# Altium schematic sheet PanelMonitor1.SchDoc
size 431 x 279 mm; Date: Not shown in title block; ApprovedBy: Not shown in title block; CheckedBy: Not shown in title block; Author: Not shown in title block; CompanyName: Not shown in title block; Engineer: Not shown in title block; Organization: Not shown in title block; Address1: Not shown in title block; Address2: Not shown in title block; Address3: Not shown in title block; Address4: Not shown in title block; DocumentNumber: 1; Revision: Use project parameter SCH_Rev; SheetNumber: 2; SheetTotal: 3; PageSetup: Record=PageOptions¦CenterHorizontal=True¦CenterVertical=True¦PrintScale=0.64¦XCorrection=1.00¦YCorrection=1.00¦PrintKind=0¦BorderSize=5000000¦LeftOffset=0¦BottomOffset=0¦Orientation=2¦PaperLength=1000¦PaperWidth=1000¦Scale=100¦PaperSource=15¦PrintQuality=600¦MediaType=1¦DitherType=10¦PrintScaleMode=1¦PaperKind=Letter
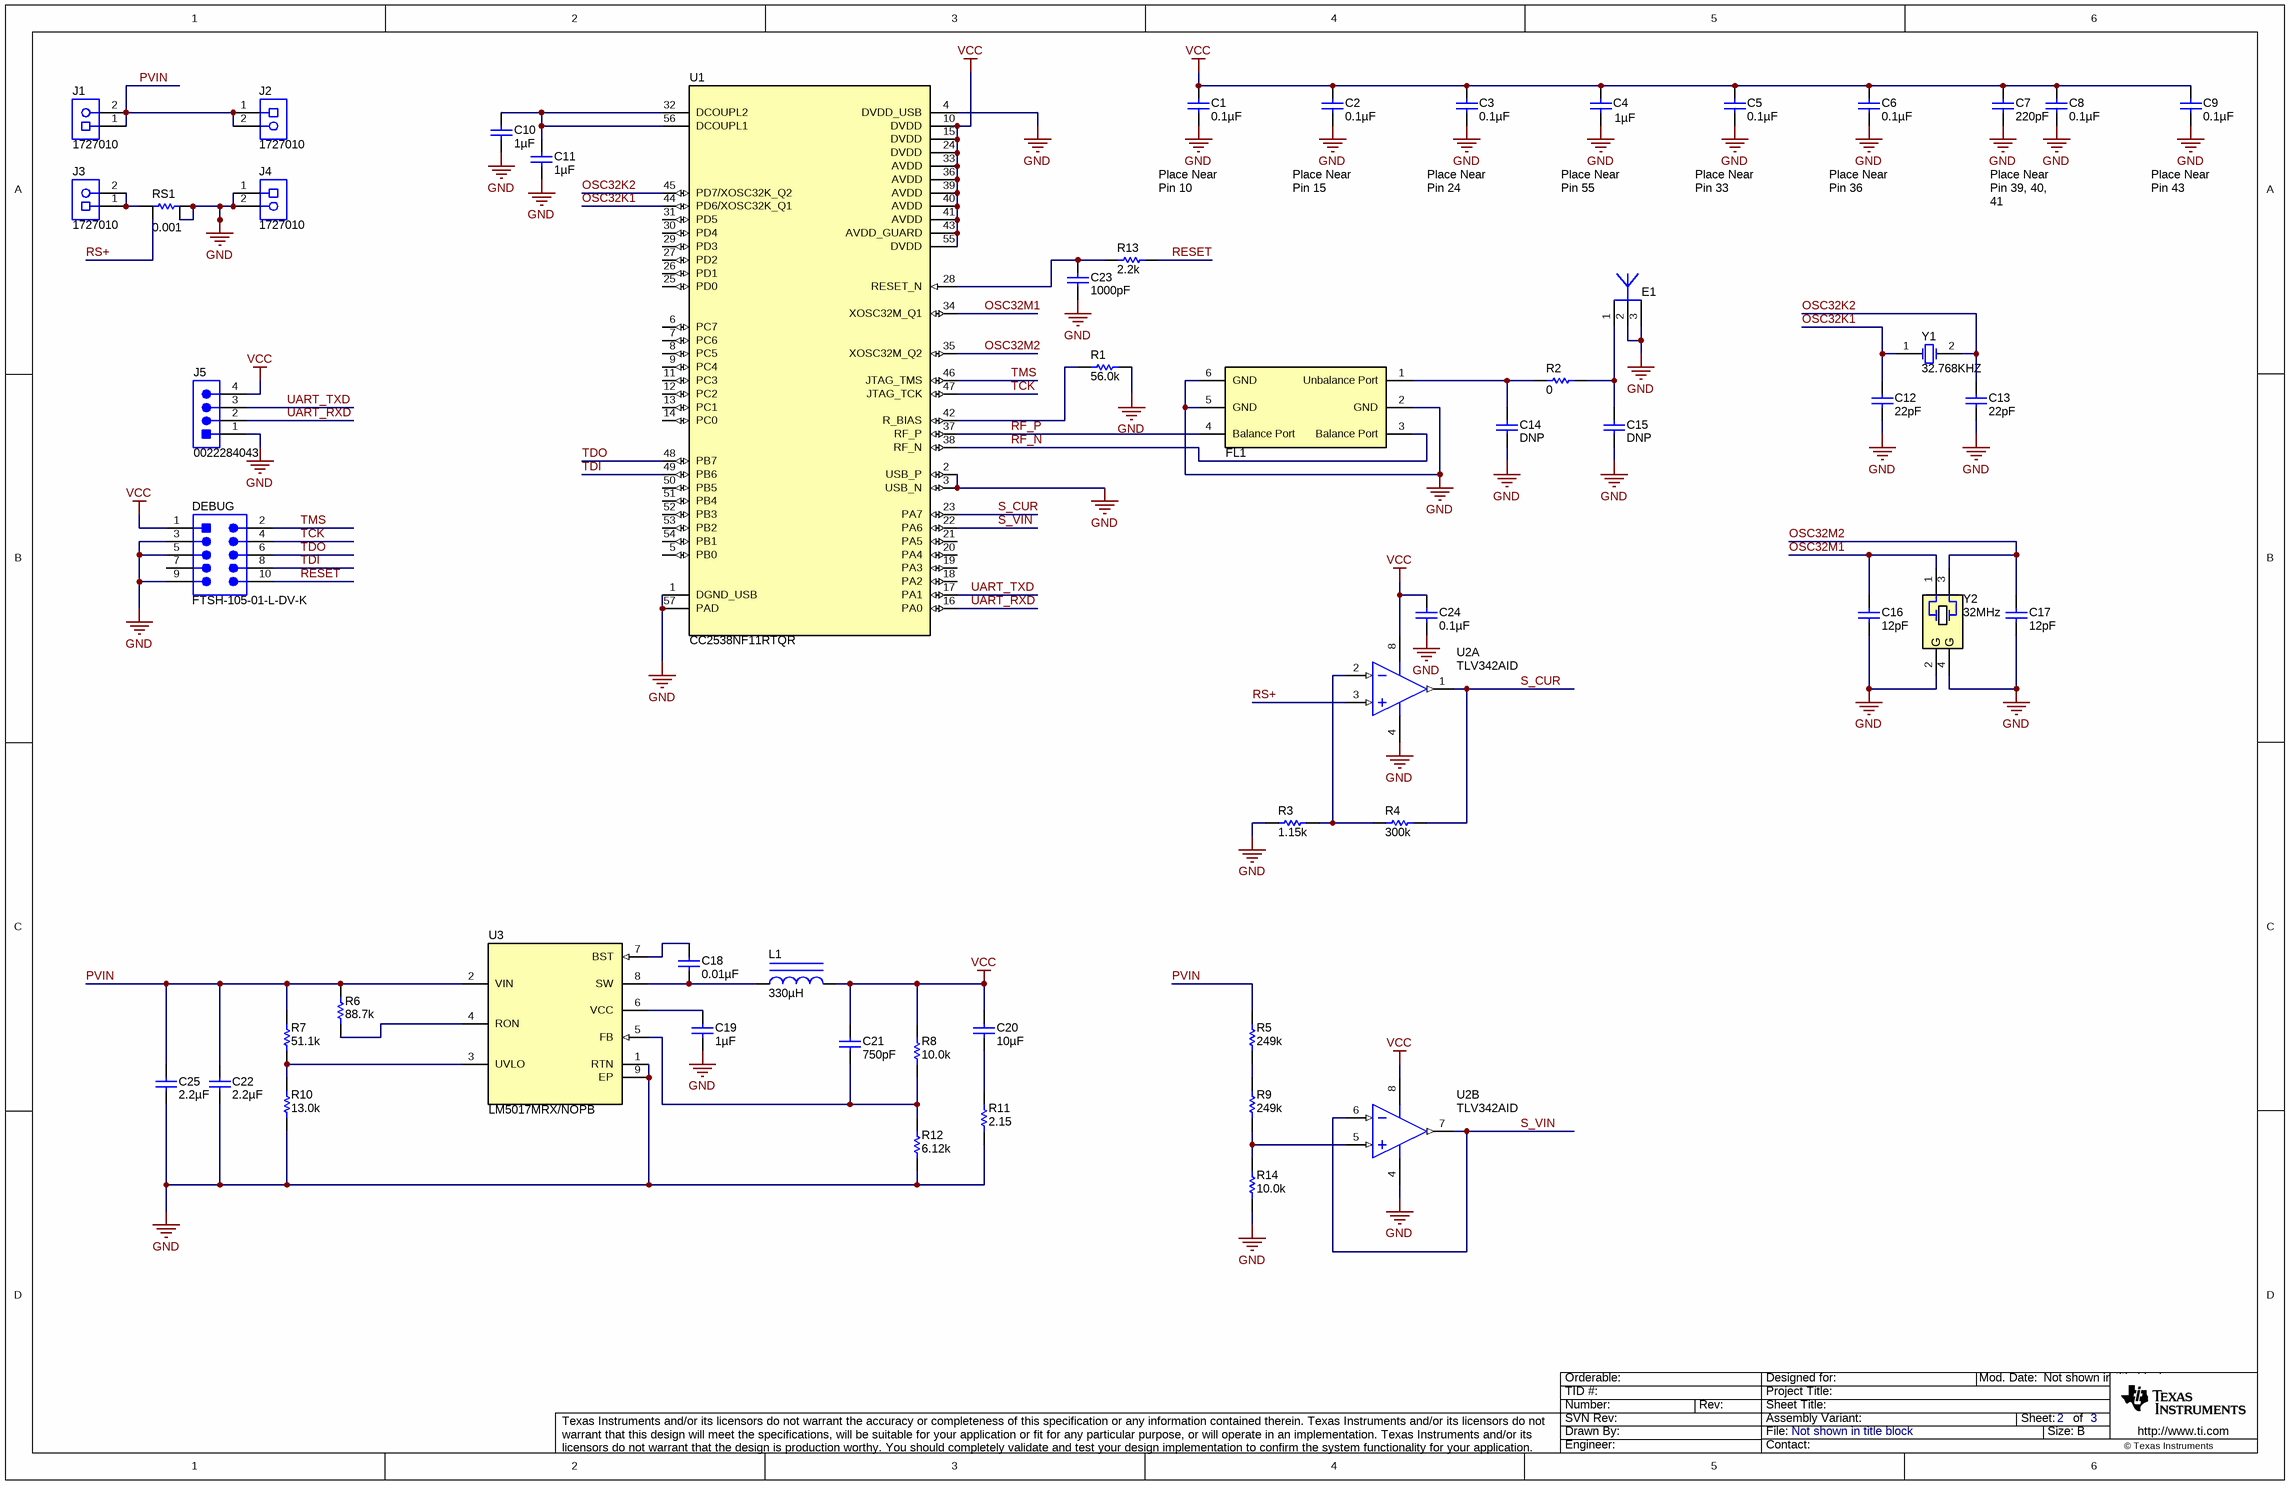
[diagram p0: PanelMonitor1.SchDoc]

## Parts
C1  ValueDisplayed: 0.1µF  [0402]  (hidden comment: GRM155R70J104KA01D)
C2  ValueDisplayed: 0.1µF  [0402]  (hidden comment: GRM155R70J104KA01D)
C3  ValueDisplayed: 0.1µF  [0402]  (hidden comment: GRM155R70J104KA01D)
C4  ValueDisplayed: 1µF  [0402]  (hidden comment: GRM155R61A105KE15D)
C5  ValueDisplayed: 0.1µF  [0402]  (hidden comment: GRM155R70J104KA01D)
C6  ValueDisplayed: 0.1µF  [0402]  (hidden comment: GRM155R70J104KA01D)
C7  ValueDisplayed: 220pF  [0402]  (hidden comment: GRM1555C1H221JA01D)
C8  ValueDisplayed: 0.1µF  [0402]  (hidden comment: GRM155R70J104KA01D)
C9  ValueDisplayed: 0.1µF  [0402]  (hidden comment: GRM155R70J104KA01D)
C10  ValueDisplayed: 1µF  [0402]  (hidden comment: GRM155R61A105KE15D)
C11  ValueDisplayed: 1µF  [0402]  (hidden comment: GRM155R61A105KE15D)
C12  ValueDisplayed: 22pF  [0402]  (hidden comment: GRM1555C1H220JA01D)
C13  ValueDisplayed: 22pF  [0402]  (hidden comment: GRM1555C1H220JA01D)
C14  ValueDisplayed: DNP  [0402]  (hidden comment: 0402YC132KAT2A)
C15  ValueDisplayed: DNP  [0402]  (hidden comment: 0402YC132KAT2A)
C16  ValueDisplayed: 12pF  [0402]  (hidden comment: GRM1555C1H120JA01D)
C17  ValueDisplayed: 12pF  [0402]  (hidden comment: GRM1555C1H120JA01D)
C18  ValueDisplayed: 0.01µF  [0402]  (hidden comment: GRM155R61C103KA01D)
C19  ValueDisplayed: 1µF  [0603]  (hidden comment: GRM188R61C105KA93D)
C20  ValueDisplayed: 10µF  [0603]  (hidden comment: GRM188R60J106ME47D)
C21  ValueDisplayed: 750pF  [0402]  (hidden comment: GRM1555C1H751JA01D)
C22  ValueDisplayed: 2.2µF  [1210_270]  (hidden comment: GRM32ER72A225KA35L)
C23  ValueDisplayed: 1000pF  [0402]  (hidden comment: GRM155R71H102KA01D)
C24  ValueDisplayed: 0.1µF  [0402]  (hidden comment: C0402C104K4RACAUTO)
C25  ValueDisplayed: 2.2µF  [1210_270]  (hidden comment: GRM32ER72A225KA35L)
DEBUG  FTSH-105-01-L-DV-K  [Samtec_FTSH-105-01-x-DV-K]
E1  ANTENNA_DN007A  [ANTENNA_DN007A]  (value not drawn)  (net tie)
FL1  LFB182G45BG5D920  [Murata_LFB182G45BG5D920]  (value not drawn)
J1  1727010  [PhoenixConact_1727010]
J2  1727010  [PhoenixConact_1727010]
J3  1727010  [PhoenixConact_1727010]
J4  1727010  [PhoenixConact_1727010]
J5  0022284043  [Molex_0022284043]
L1  ValueDisplayed: 330µH  [LPS5030]  (hidden comment: LPS5030-334MLB)
R1  ValueDisplayed: 56.0k  [0402]  (hidden comment: RK73H1ETTP5602F)
R2  ValueDisplayed: 0  [0402]  (hidden comment: CRCW04020000Z0ED)
R3  ValueDisplayed: 1.15k  [0402]  (hidden comment: CRCW04021K15FKED)
R4  ValueDisplayed: 300k  [0402]  (hidden comment: CRCW0402300KFKED)
R5  ValueDisplayed: 249k  [1206]  (hidden comment: CRCW1206249KFKEA)
R6  ValueDisplayed: 88.7k  [0402]  (hidden comment: CRCW040288K7FKED)
R7  ValueDisplayed: 51.1k  [0402]  (hidden comment: CRCW040251K1FKED)
R8  ValueDisplayed: 10.0k  [0402]  (hidden comment: CRCW040210K0FKED)
R9  ValueDisplayed: 249k  [1206]  (hidden comment: CRCW1206249KFKEA)
R10  ValueDisplayed: 13.0k  [0402]  (hidden comment: CRCW040213K0FKED)
R11  ValueDisplayed: 2.15  [0402]  (hidden comment: CRCW04022R15FKED)
R12  ValueDisplayed: 6.12k  [0805_HV]  (hidden comment: RT0805BRD076K12L)
R13  ValueDisplayed: 2.2k  [0402]  (hidden comment: CRCW04022K20JNED)
R14  ValueDisplayed: 10.0k  [0805_HV]  (hidden comment: ERJ-6ENF1002V)
RS1  ValueDisplayed: 0.001  [LRMAP3920B-R001FT]  (hidden comment: LRMAP3920B-R001FT)
U1  CC2538NF11RTQR  [RTQ0056C]
U2  TLV342AID  [D0008A_N]  (parts A,B of 2)
U3  LM5017MRX/NOPB  [DDA0008B_N]
Y1  Frequency: 32.768KHZ  [Epson_FC-12M]  (hidden comment: FC-12M 32.7680KA-A3)
Y2  Frequency: 32MHz  [Epson_FA-128]  (hidden comment: FA-128 32.0000MF20X-K3)

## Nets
GND: C1.2 C2.2 C3.2 C4.2 C5.2 C6.2 C7.2 C8.2 C9.2 C10.2 C11.2 C12.2 C13.2 C14.2 C15.2 C16.2 C17.2 C19.2 C22.1 C23.2 C24.2 C25.1 DEBUG.3 DEBUG.5 DEBUG.9 E1.2 E1.3 FL1.2(GND) FL1.5(GND) FL1.6(GND) J4.1 J4.2 J5.1 R1.2 R3.1 R10.1 R11.1 R12.1 R14.1 RS1.1 RS1.3 U1.1(DGND_USB) U1.2(USB_P) U1.3(USB_N) U1.4(DVDD_USB) U1.57(PAD) U2.4(GND) U3.1(RTN) U3.9(EP) Y2.2(GND) Y2.4(GND)
VCC: C1.1 C2.1 C3.1 C4.1 C5.1 C6.1 C7.1 C8.1 C9.1 C20.1 C21.1 C24.1 DEBUG.1 J5.4 L1.2 R8.2 U1.10(DVDD) U1.15(DVDD) U1.24(DVDD) U1.33(AVDD) U1.36(AVDD) U1.39(AVDD) U1.40(AVDD) U1.41(AVDD) U1.43(AVDD_GUARD) U1.55(DVDD) U2.8(V+)
OSC32K1: C12.1 U1.44(PD6/XOSC32K_Q1) Y1.1(OSC1)
OSC32K2: C13.1 U1.45(PD7/XOSC32K_Q2) Y1.2(OSC2)
OSC32M1: C16.1 U1.34(XOSC32M_Q1) Y2.1
OSC32M2: C17.1 U1.35(XOSC32M_Q2) Y2.3
PVIN: C22.2 C25.2 J1.1 J1.2 J2.1 J2.2 R5.2 R6.2 R7.2 U3.2(VIN)
RESET: DEBUG.10 R13.2
RF_N: FL1.3(Balance_Port) U1.38(RF_N)
RF_P: FL1.4(Balance_Port) U1.37(RF_P)
RS+: RS1.4 U2.3(IN1+)
S_CUR: R4.2 U1.23(PA7) U2.1(OUT1)
S_VIN: U1.22(PA6) U2.6(IN2-) U2.7(OUT2)
TCK: DEBUG.4 U1.47(JTAG_TCK)
TDI: DEBUG.8 U1.49(PB6)
TDO: DEBUG.6 U1.48(PB7)
TMS: DEBUG.2 U1.46(JTAG_TMS)
UART_RXD: J5.2 U1.16(PA0)
UART_TXD: J5.3 U1.17(PA1)
NetC10_1: C10.1 C11.1 U1.32(DCOUPL2) U1.56(DCOUPL1)
NetC14_1: C14.1 FL1.1(Unbalance_Port) R2.1
NetC15_1: C15.1 E1.1 R2.2
NetC18_1: C18.1 U3.7(BST)
NetC18_2: C18.2 L1.1 U3.8(SW)
NetC19_1: C19.1 U3.6(VCC)
NetC20_2: C20.2 R11.2
NetC21_2: C21.2 R8.1 R12.2 U3.5(FB)
NetC23_1: C23.1 R13.1 U1.28(RESET_N)
NetJ3_1: J3.1 J3.2 RS1.2
NetR1_1: R1.1 U1.42(R_BIAS)
NetR3_2: R3.2 R4.1 U2.2(IN1-)
NetR5_1: R5.1 R9.2
NetR6_1: R6.1 U3.4(RON)
NetR7_1: R7.1 R10.2 U3.3(UVLO)
NetR9_1: R9.1 R14.2 U2.5(IN2+)

Not connected (* = marked no-connect by the designer): DEBUG 7; U1 5(PB0) 6(PC7) 7(PC6) 8(PC5) 9(PC4) 11(PC3) 12(PC2) 13(PC1) 14(PC0) 18(PA2) 19(PA3) 20(PA4) 21(PA5) 25(PD0) 26(PD1) 27(PD2) 29(PD3) 30(PD4) 31(PD5) 50(PB5) 51(PB4) 52(PB3) 53(PB2) 54(PB1)

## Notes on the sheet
- Place Near
  Pin 10
- Place Near
  Pin 15
- Place Near
  Pin 24
- Place Near
  Pin 55
- Place Near
  Pin 33
- Place Near
  Pin 36
- Place Near
  Pin 39, 40, 41
- Place Near
  Pin 43

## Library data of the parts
C1 = GRM155R70J104KA01D: CAP, CERM, 0.1 µF, 6.3 V, +/- 10%, X7R, 0402; Manufacturer: MuRata; Polarized: N; CompType: Capacitor; VALUE: 0.1uF; U/M: EA; Cap_F: 0.0000001; Tolerance_%: 10; Value1: Unknown; VDC_V: 6.3; Value2: 6.3V; TaMin_C: -55; TaMax_C: 125; SizeArea_mm2: 0.5; SizeAreaWB_mm2: 3; SizeX_mm: 1; SizeZ_mm: 0.6; AEC Category: Q200
C2 C3 C5 C6 C8 C9 = GRM155R70J104KA01D: CAP, CERM, 0.1 µF, 6.3 V, +/- 10%, X7R, 0402; Manufacturer: MuRata; Polarized: N; CompType: Capacitor; Value: 0.1uF; U/M: EA; Cap_F: 0.0000001; Tolerance_%: 10; Value1: Unknown; VDC_V: 6.3; Value2: 6.3V; TaMin_C: -55; TaMax_C: 125; SizeArea_mm2: 0.5; SizeAreaWB_mm2: 3; SizeX_mm: 1; SizeZ_mm: 0.6; AEC Category: Q200
C4 C10 C11 = GRM155R61A105KE15D: CAP, CERM, 1 µF, 10 V, +/- 10%, X5R, 0402; Manufacturer: MuRata; Polarized: N; CompType: Capacitor; Value: 1uF; U/M: EA; Cap_F: 0.000001; Tolerance_%: 10; Value1: Unknown; Value2: 10V; TaMin_C: -55; TaMax_C: 85; SizeArea_mm2: 0.5; SizeAreaWB_mm2: 3; SizeX_mm: 1; SizeZ_mm: 0.6; AEC Category: Q200
C7 = GRM1555C1H221JA01D: CAP, CERM, 220 pF, 50 V, +/- 5%, C0G/NP0, 0402; Manufacturer: MuRata; Polarized: N; CompType: Capacitor; Value: 220pF; U/M: EA; Cap_F: 0.00000000022; Tolerance_%: 5; Value1: Unknown; VDC_V: 50; Value2: 50V; TaMin_C: -55; TaMax_C: 125; SizeArea_mm2: 0.5; SizeAreaWB_mm2: 3; SizeX_mm: 1; SizeZ_mm: 0.6; AEC Category: Q200
C12 C13 = GRM1555C1H220JA01D: CAP, CERM, 22 pF, 50 V, +/- 5%, C0G/NP0, 0402; Manufacturer: MuRata; Polarized: N; CompType: Capacitor; Value: 22pF; U/M: EA; Cap_F: 0.000000000022; Tolerance_%: 5; Value1: Unknown; VDC_V: 50; Value2: 50V; TaMin_C: -55; TaMax_C: 125; SizeArea_mm2: 0.5; SizeAreaWB_mm2: 3; SizeX_mm: 1; SizeZ_mm: 0.6; AEC Category: Q200
C14 C15 = 0402YC132KAT2A: CAP, CERM, 1300 pF, 16 V, +/- 10%, X7R, 0402; Manufacturer: AVX; Polarized: N; CompType: Capacitor; Value: DNP; U/M: EA; Cap_F: 0.0000000013; Tolerance_%: 10; Value1: Unknown; VDC_V: 16; Value2: 16V; TaMin_C: -55; TaMax_C: 125; SizeArea_mm2: 0.5; SizeAreaWB_mm2: 3; SizeX_mm: 1; SizeZ_mm: 0.6; AEC Category: Q200
C16 C17 = GRM1555C1H120JA01D: CAP, CERM, 12 pF, 50 V, +/- 5%, C0G/NP0, 0402; Manufacturer: MuRata; Polarized: N; CompType: Capacitor; Value: 12pF; U/M: EA; Cap_F: 0.000000000012; Tolerance_%: 5; Value1: Unknown; VDC_V: 50; Value2: 50V; TaMin_C: -55; TaMax_C: 125; SizeArea_mm2: 0.5; SizeAreaWB_mm2: 3; SizeX_mm: 1; SizeZ_mm: 0.6; AEC Category: Q200
C18 = GRM155R61C103KA01D: CAP, CERM, 0.01 µF, 16 V, +/- 10%, X5R, 0402; Manufacturer: MuRata; Polarized: N; CompType: Capacitor; Value: 0.01uF; U/M: EA; Cap_F: 0.00000001; Tolerance_%: 10; Value1: Unknown; VDC_V: 16; Value2: 16V; TaMin_C: -55; TaMax_C: 85; SizeArea_mm2: 0.5; SizeAreaWB_mm2: 3; SizeX_mm: 1; SizeZ_mm: 0.6; AEC Category: Q200
C19 = GRM188R61C105KA93D: CAP, CERM, 1 µF, 16 V, +/- 10%, X5R, 0603; Manufacturer: MuRata; Polarized: N; CompType: Capacitor; Value: 1uF; U/M: EA; Cap_F: 0.000001; Tolerance_%: 10; Value1: Unknown; VDC_V: 16; Value2: 16V; TaMin_C: -55; TaMax_C: 85; SizeArea_mm2: 1.28; SizeAreaWB_mm2: 4.68; SizeX_mm: 1.6; SizeY_mm: 0.8; SizeZ_mm: 1; AEC Category: Q200
C20 = GRM188R60J106ME47D: CAP, CERM, 10 µF, 6.3 V, +/- 20%, X5R, 0603; Manufacturer: MuRata; Polarized: N; CompType: Capacitor; Value: 10uF; U/M: EA; Cap_F: 0.00001; Tolerance_%: 20; ESR_ohm: 0.009; Value1: 0.009 ohm; VDC_V: 6.3; Value2: 6.3V; IRMS_A: 2.74; TaMin_C: -55; TaMax_C: 125; SizeArea_mm2: 1.28; SizeAreaWB_mm2: 4.68; SizeX_mm: 1.6; SizeY_mm: 0.8; SizeZ_mm: 1; AEC Category: Q200
C21 = GRM1555C1H751JA01D: CAP, CERM, 750 pF, 50 V, +/- 5%, C0G/NP0, 0402; Manufacturer: MuRata; Polarized: N; CompType: Capacitor; Value: 750pF; U/M: EA; Cap_F: 0.00000000075; Tolerance_%: 5; Value1: Unknown; VDC_V: 50; Value2: 50V; TaMin_C: -55; TaMax_C: 125; SizeArea_mm2: 0.5; SizeAreaWB_mm2: 3; SizeX_mm: 1; SizeZ_mm: 0.6; AEC Category: Q200
C22 C25 = GRM32ER72A225KA35L: CAP, CERM, 2.2 µF, 100 V, +/- 10%, X7R, 1210; Manufacturer: MuRata; Polarized: N; CompType: Capacitor; Value: 2.2uF; U/M: EA; Cap_F: 0.0000022; Tolerance_%: 10; ESR_ohm: 0.007; Value1: 0.007 ohm; VDC_V: 100; Value2: 100V; IRMS_A: 4.4; TaMin_C: -55; TaMax_C: 125; Cap_Case: 1210; SizeArea_mm2: 8; SizeAreaWB_mm2: 14.7; SizeX_mm: 3.2; SizeY_mm: 2.5; SizeZ_mm: 2.7; AEC Category: Q200
C23 = GRM155R71H102KA01D: CAP, CERM, 1000 pF, 50 V, +/- 10%, X7R, 0402; Manufacturer: MuRata; Polarized: N; CompType: Capacitor; Value: 1000pF; U/M: EA; Cap_F: 0.000000001; Tolerance_%: 10; Value1: Unknown; VDC_V: 50; Value2: 50V; TaMin_C: -55; TaMax_C: 125; SizeArea_mm2: 0.5; SizeAreaWB_mm2: 3; SizeX_mm: 1; SizeZ_mm: 0.6; AEC Category: Q200
C24 = C0402C104K4RACAUTO: CAP, CERM, 0.1 µF, 16 V, +/- 10%, X7R, AEC-Q200 Grade 1, 0402; Manufacturer: Kemet; Polarized: N; CompType: Capacitor; Value: 0.1uF; U/M: EA; Cap_F: 0.0000001; Tolerance_%: 10; Value1: Unknown; VDC_V: 16; Value2: 16V; TaMin_C: -55; TaMax_C: 125; SizeArea_mm2: 0.5; SizeAreaWB_mm2: 3; SizeX_mm: 1; SizeZ_mm: 0.6; AEC Category: Q200; AEC Qualified: Y
DEBUG = FTSH-105-01-L-DV-K: Header(Shrouded), 1.27mm, 5x2, Gold, SMT; Manufacturer: Samtec; SymbolCreator: a0412235; Pitch_mm: 1.27; Gender: Male; Shrouded: Y; Row_Count: 2; Current_A: 3.3
E1 = ANTENNA_DN007A: 2.4GHz PCB Antenna.  There is nothing to buy or mount.; SymbolCreator: a0412235
FL1 = LFB182G45BG5D920: Filter, BandPass, 2.45GHz, SMD; Manufacturer: MuRata; SymbolCreator: Altium
J1-J4 = 1727010: Conn Term Block, 2POS, 3.81mm, TH; Manufacturer: Phoenix Contact; SymbolCreator: a0412235; CompType: Terminal Block
J5 = 0022284043: Header, 2.54mm, 4x1, Tin, TH; Manufacturer: Molex; SymbolCreator: a0412235; Pitch_mm: 2.54; Gender: Male; Shrouded: N; Row_Count: 1; Current_A: 4; Voltage_V: 250; Cert_UL: Y
L1 = LPS5030-334MLB: Inductor, Shielded Drum Core, Ferrite, 330 µH, 0.2 A, 1.8 ohm, SMD; Manufacturer: Coilcraft; Value: 330uH; Ind_H: 330.0E-6; Imax_A: 0.2; Irms: 0.42A @ 40C rise; Isat: 0.2A @ 30% inductance drop; DCR_ohm: 1.8; Value1: 1.8 ohm; Value2: 0.2A; AEC Category: Q200
R1 = RK73H1ETTP5602F: RES, 56.0 k, 1%, 0.063 W, AEC-Q200 Grade 0, 0402; Manufacturer: KOA Speer; CompType: Resistor; Value: 56.0k; Res_ohm: 56000; Value_Code: 56k0; Tolerance_%: 1; Power_W: 0.063; Value2: 0.063W; VDC_V: 50; TempCo: 100 ppm/C; SizeArea_mm2: 0.5; SizeZ_mm: 0.6; U/M: EA; AEC Category: Q200; AEC Qualified: Y; AEC Grade: 0
R2 = CRCW04020000Z0ED: RES, 0, 5%, 0.063 W, 0402; Manufacturer: Vishay-Dale; CompType: Resistor; Value: 0; Value_Code: 0000; Tolerance_%: 5; Power_W: 0.063; Value2: 0.063W; VDC_V: 50; TempCo: 200 ppm/C; SizeArea_mm2: 0.5; SizeX_mm: 1; SizeZ_mm: 0.6; EIA_Code: E24; U/M: EA; AEC Category: Q200
R3 = CRCW04021K15FKED: RES, 1.15 k, 1%, 0.063 W, 0402; Manufacturer: Vishay-Dale; CompType: Resistor; Value: 1.15k; Res_ohm: 1150; Value_Code: 1k15; Tolerance_%: 1; Power_W: 0.063; Value2: 0.063W; VDC_V: 50; TempCo: 100 ppm/C; SizeArea_mm2: 0.5; SizeZ_mm: 0.6; EIA_Code: E96; U/M: EA; AEC Category: Q200
R4 = CRCW0402300KFKED: RES, 300 k, 1%, 0.063 W, AEC-Q200 Grade 0, 0402; Manufacturer: Vishay-Dale; CompType: Resistor; Value: 300k; Res_ohm: 300000; Tolerance_%: 1; Power_W: 0.063; Value2: 0.063W; VDC_V: 50; TempCo: 100 ppm/C; SizeArea_mm2: 0.5; SizeZ_mm: 0.6; U/M: EA; AEC Category: Q200; AEC Qualified: Y; AEC Grade: 0
R5 R9 = CRCW1206249KFKEA: RES, 249 k, 1%, 0.25 W, 1206; Manufacturer: Vishay-Dale; CompType: Resistor; Value: 249k; Res_ohm: 249000; Tolerance_%: 1; Power_W: 0.25; Value2: 0.25W; VDC_V: 200; TempCo: 100 ppm/C; SizeArea_mm2: 5.12; SizeX_mm: 3.2; SizeY_mm: 1.6; SizeZ_mm: 1.35; EIA_Code: E96; U/M: EA; AEC Category: Q200
R6 = CRCW040288K7FKED: RES, 88.7 k, 1%, 0.063 W, 0402; Manufacturer: Vishay-Dale; CompType: Resistor; Value: 88.7k; Res_ohm: 88700; Value_Code: 88k7; Tolerance_%: 1; Power_W: 0.063; Value2: 0.063W; VDC_V: 50; TempCo: 100 ppm/C; SizeArea_mm2: 0.5; SizeZ_mm: 0.6; EIA_Code: E96; U/M: EA; AEC Category: Q200
R7 = CRCW040251K1FKED: RES, 51.1 k, 1%, 0.063 W, 0402; Manufacturer: Vishay-Dale; CompType: Resistor; Value: 51.1k; Res_ohm: 51100; Value_Code: 51k1; Tolerance_%: 1; Power_W: 0.063; Value2: 0.063W; VDC_V: 50; TempCo: 100 ppm/C; SizeArea_mm2: 0.5; SizeZ_mm: 0.6; EIA_Code: E96; U/M: EA; AEC Category: Q200
R8 = CRCW040210K0FKED: RES, 10.0 k, 1%, 0.063 W, 0402; Manufacturer: Vishay-Dale; CompType: Resistor; Value: 10.0k; Res_ohm: 10000; Value_Code: 10k0; Tolerance_%: 1; Power_W: 0.063; Value2: 0.063W; VDC_V: 50; TempCo: 100 ppm/C; SizeArea_mm2: 0.5; SizeZ_mm: 0.6; EIA_Code: E96; U/M: EA; AEC Category: Q200
R10 = CRCW040213K0FKED: RES, 13.0 k, 1%, 0.063 W, 0402; Manufacturer: Vishay-Dale; CompType: Resistor; Value: 13.0k; Res_ohm: 13000; Value_Code: 13k0; Tolerance_%: 1; Power_W: 0.063; Value2: 0.063W; VDC_V: 50; TempCo: 100 ppm/C; SizeArea_mm2: 0.5; SizeZ_mm: 0.6; EIA_Code: E96; U/M: EA; AEC Category: Q200
R11 = CRCW04022R15FKED: RES, 2.15, 1%, 0.063 W, 0402; Manufacturer: Vishay-Dale; CompType: Resistor; Value: 2.15; Value_Code: 2R15; Tolerance_%: 1; Power_W: 0.063; Value2: 0.063W; VDC_V: 50; TempCo: 100 ppm/C; SizeArea_mm2: 0.5; SizeZ_mm: 0.6; EIA_Code: E96; U/M: EA; AEC Category: Q200
R12 = RT0805BRD076K12L: RES, 6.12 k, 0.1%, 0.125 W, 0805; Manufacturer: Yageo America; CompType: Resistor; Value: 6.12k; Res_ohm: 6120; Value_Code: 6k12; Tolerance_%: 0.1; Power_W: 0.125; Value2: 0.125W; VDC_V: 150; TempCo: 25 ppm/C; SizeArea_mm2: 2.5; SizeX_mm: 2; SizeY_mm: 1.25; SizeZ_mm: 1.45; EIA_Code: E192; U/M: EA; AEC Category: Q200
R13 = CRCW04022K20JNED: RES, 2.2 k, 5%, 0.063 W, 0402; Manufacturer: Vishay-Dale; CompType: Resistor; Value: 2.2k; Res_ohm: 2200; Value_Code: 2k20; Tolerance_%: 5; Power_W: 0.063; Value2: 0.063W; VDC_V: 50; TempCo: 200 ppm/C; SizeArea_mm2: 0.5; SizeX_mm: 1; SizeZ_mm: 0.6; EIA_Code: E24; U/M: EA; AEC Category: Q200
R14 = ERJ-6ENF1002V: RES, 10.0 k, 1%, 0.125 W, 0805; Manufacturer: Panasonic; CompType: Resistor; Value: 10.0k; Res_ohm: 10000; Value_Code: 10k0; Tolerance_%: 1; Power_W: 0.125; Value2: 0.125W; TempCo: 100 ppm/C; SizeArea_mm2: 2.5; SizeX_mm: 2; SizeY_mm: 1.25; SizeZ_mm: 1.45; EIA_Code: E96; U/M: EA; AEC Category: Q200
RS1 = LRMAP3920B-R001FT: RES, 0.001, 1%, 4 W, AEC-Q200 Grade 0, 3920; Manufacturer: TT Electronics/IRC; CompType: Resistor; Value: 0.001; Value_Code: 1L000; Tolerance_%: 1; Power_W: 4; Value2: 4W; TempCo: 170 ppm/C; EIA_Code: E96; U/M: EA; AEC Category: Q200; AEC Qualified: Y; AEC Grade: 0
U1 = CC2538NF11RTQR: A Powerful System-On-Chip for 2.4-GHz IEEE 802.15.4, 6LoWPAN and ZigBee Applications, RTQ0056F; Alternate PartNumber: CC2538NF11RTQT; Manufacturer: Texas Instruments; SymbolCreator: a0799628; SizeArea_mm2: 64; SizeAreaWB_mm2: 100; SizeX_mm: 8; SizeZ_mm: 1; CompType: IC; U/M: EA
U2 = TLV342AID: Low-Voltage, Rail-To-Rail Output CMOS Operational Amplifier, 1.5 to 5.5 V, -40 to 125 degC, 8-pin SOIC (D0008A), Green (RoHS & no Sb/Br); Alternate Manufacturer: Texas Instruments; Alternate PartNumber: Equivalent; CMRR(Min)(dB): 50; GBW(Typ)(MHz): 2.2; IIB(Max)(pA): 3000; Iq per channel(Max)(mA): 0.15; Number of Channels: 2; Offset Drift(Typ)(uV/C): 1.9; Rating: Catalog; Slew Rate(Typ)(V/us): 0.9; Sub Family: General Purpose Amplifier, Low Power Amp (<=500uA), Low Supply Voltage Amplifier (<=2.7V); Total Supply Voltage(Max)(+5V is 5, +/-5V is 10): 5.5; Total Supply Voltage(Min)(+5V is 5, +/-5V is 10): 1.5; Vio (25C)(Max)(mV): 1.25; Vn at 1kHz(Typ)(nV/rtHz): 33
U3 = LM5017MRX/NOPB: 100V, 600mA Constant On-Time Synchronous Buck Regulator, DDA0008B; Alternate PartNumber: LM5017MR/NOPB; Manufacturer: Texas Instruments; SymbolCreator: a0412235; SizeArea_mm2: 31; SizeAreaWB_mm2: 57.4; SizeX_mm: 5; SizeY_mm: 6.2; SizeZ_mm: 1.7; CompType: IC; U/M: EA
Y1 = FC-12M 32.7680KA-A3: Crystal, 32.768kHz, 12.5pF, SMD; Manufacturer: Epson; SymbolCreator: a0412235; U/M: EA; TaMin_C: -40; TaMax_C: 85; Frequency Stability: ±20ppm
Y2 = FA-128 32.0000MF20X-K3: Crystal, 32MHz, 10pF, SMD; Manufacturer: Epson; SymbolCreator: a0412235; U/M: EA; TaMin_C: -40; TaMax_C: 85; Frequency Stability: ±20ppm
